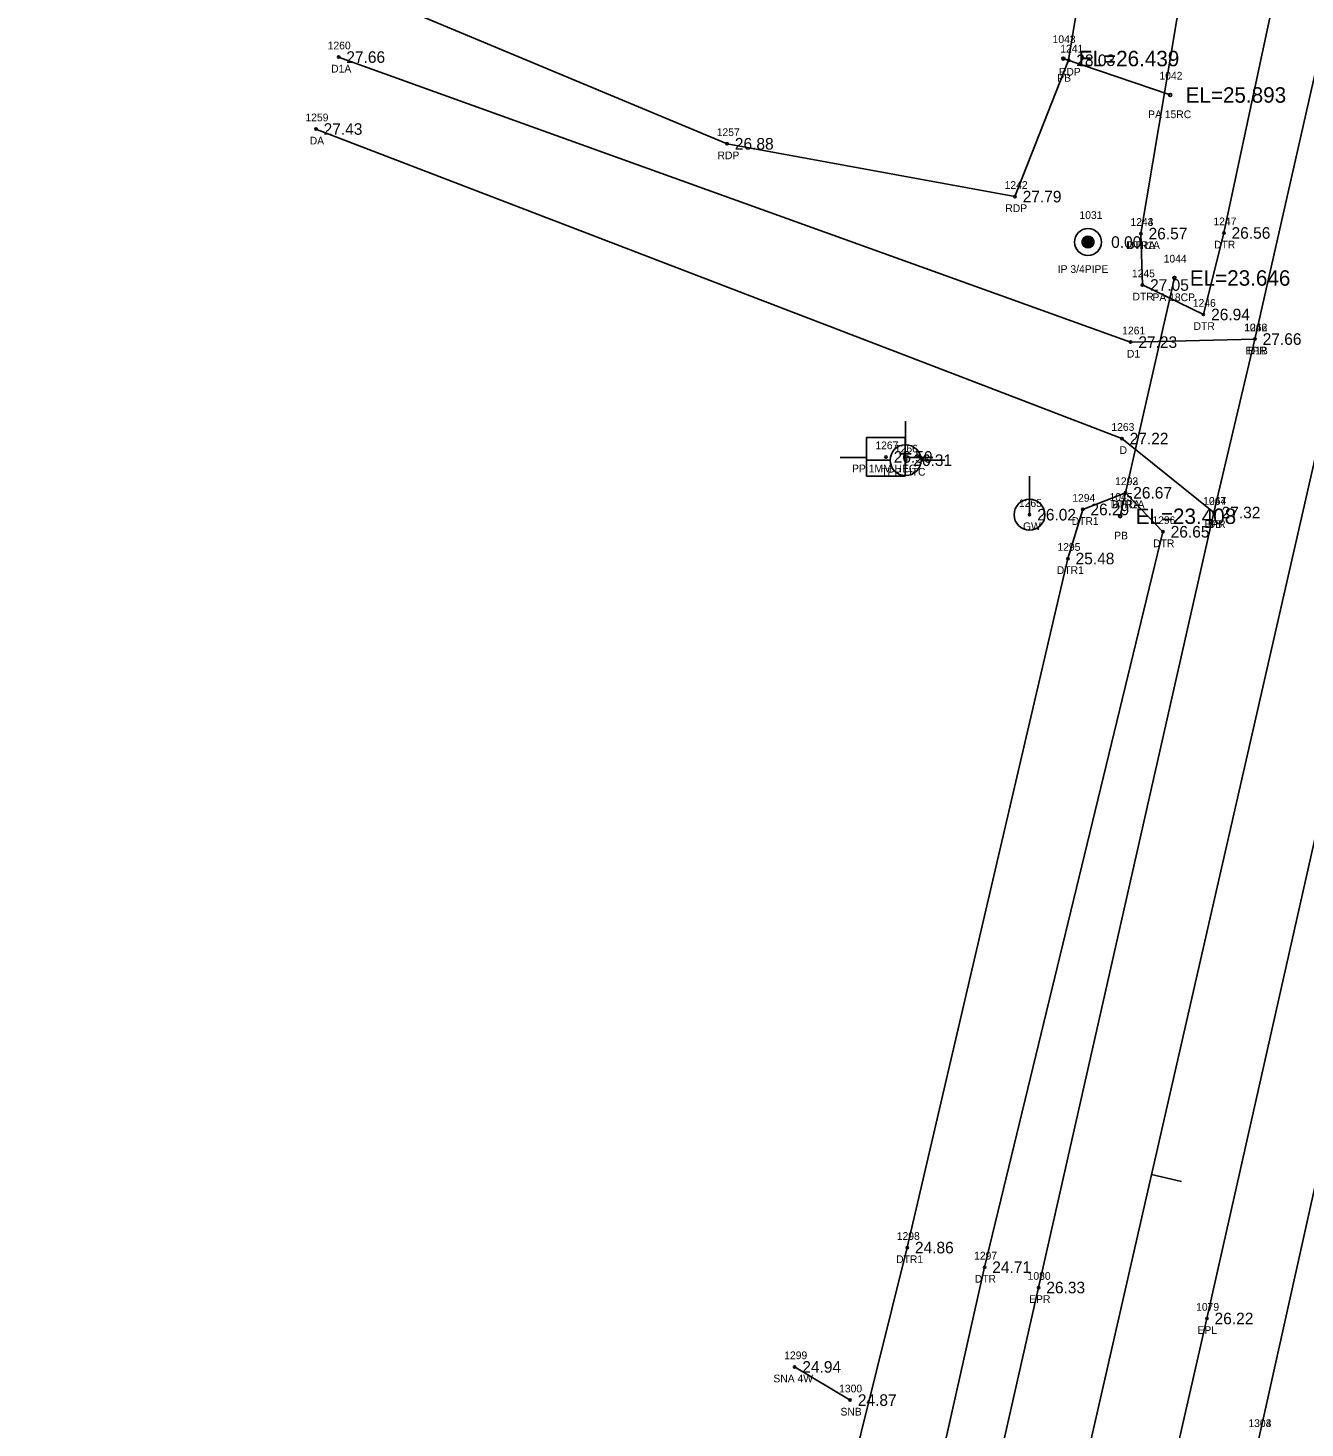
# Model space of a CAD drawing. Extents: x 2654414 to 2656963, y 761776 to 764965.
# Drawn here: x 2655843.9 to 2656009.2, y 764411.4 to 764592.8 of the extents above; entities that cross this region are included whole.
import ezdxf

# ---------------------------------------------------------------- set-up
doc = ezdxf.new("R2010")
doc.units = 0
for name, color, linetype in [('Default', 7, 'Continuous'), ('RD_EX_BldgApp', 7, 'Continuous'), ('RD_EX_BldgApp_txCode', 7, 'Continuous'), ('RD_EX_DR_ErosCtrl', 7, 'Continuous'), ('RD_EX_DR_ErosCtrl_txCode', 7, 'Continuous'), ('RD_EX_DR_Pipe', 7, 'Continuous'), ('RD_EX_DR_Pipe_txCode', 7, 'Continuous'), ('RD_EX_Driveway', 7, 'Continuous'), ('RD_EX_Driveway_txCode', 7, 'Continuous'), ('RD_EX_DV_Prop_txCode', 7, 'Continuous'), ('RD_EX_DV_PropPin', 7, 'Continuous'), ('RD_EX_H2O', 7, 'Continuous'), ('RD_EX_H2O_txCode', 7, 'Continuous'), ('RD_EX_Road', 7, 'Continuous'), ('RD_EX_Road_txCode', 7, 'Continuous'), ('RD_EX_TX_BldgApp_ELEV', 7, 'Continuous'), ('RD_EX_TX_DR_ErosCtrl_ELEV', 7, 'Continuous'), ('RD_EX_TX_Driveway_ELEV', 7, 'Continuous'), ('RD_EX_TX_DV_Prop_ELEV', 7, 'Continuous'), ('RD_EX_TX_H2O_ELEV', 7, 'Continuous'), ('RD_EX_TX_Road_ELEV', 7, 'Continuous'), ('RD_EX_TX_UT_ELEV', 7, 'Continuous'), ('RD_EX_UT', 7, 'Continuous'), ('RD_EX_UT_txCode', 7, 'Continuous'), ('RD_HC_Cl', 7, 'Continuous'), ('RD_HC_Data_Tic', 7, 'Continuous'), ('RD_HC_Survey_ELEV', 7, 'Continuous'), ('RD_SMD_Locator', 7, 'Continuous'), ('RD_TX_Pipe_ElevEX', 7, 'Continuous')]:
    doc.layers.add(name, color=color, linetype=linetype)

msp = doc.modelspace()

# ---------------------------------------------------------------- linework, layer by layer
at = {"layer": 'Default'}
msp.add_line((2656050.51, 764712.37), (2655383.26, 761787.51), dxfattribs=at)
at = {"layer": 'RD_EX_BldgApp'}
msp.add_line((2655943.15, 764419.36), (2655950.34, 764415.06), dxfattribs=at)
at = {"layer": 'RD_EX_DR_ErosCtrl'}
msp.add_lwpolyline([(2655930.28, 764725.72), (2655961.08, 764712.81), (2655949.1, 764679.46), (2655943.17, 764649.44), (2655951.78, 764644.09), (2655985.92, 764633.07), (2655978.62, 764588.6), (2655971.68, 764570.94), (2655934.42, 764577.78), (2655887.79, 764597.3)], dxfattribs=at)
at = {"layer": 'RD_EX_DR_Pipe'}
for p, q in [((2655991.77, 764584.1), (2655977.94, 764588.82)), ((2655992.32, 764560.4), (2655985.3, 764529.54)), ((2656020.76, 764488.83), (2656001.47, 764402.19))]:
    msp.add_line(p, q, dxfattribs=at)
at = {"layer": 'RD_EX_Driveway'}
for points in [[(2655884.12, 764589.01), (2655986.65, 764552.09), (2656002.75, 764552.49)], [(2655881.18, 764579.69), (2655985.53, 764539.6), (2655997.43, 764530.02)]]:
    msp.add_lwpolyline(points, dxfattribs=at)
at = {"layer": 'RD_EX_DV_PropPin'}
for p, q in [((2655980.4, 764564.85), (2655980.4, 764565.24)), ((2655980.43, 764564.75), (2655980.43, 764565.35)), ((2655980.47, 764564.68), (2655980.47, 764565.42)), ((2655980.5, 764564.62), (2655980.5, 764565.48)), ((2655980.54, 764564.57), (2655980.54, 764565.52)), ((2655980.57, 764564.53), (2655980.57, 764565.56)), ((2655980.61, 764564.5), (2655980.61, 764565.6)), ((2655980.64, 764564.47), (2655980.64, 764565.63)), ((2655980.68, 764564.44), (2655980.68, 764565.66)), ((2655980.71, 764564.41), (2655980.71, 764565.68)), ((2655980.75, 764564.39), (2655980.75, 764565.71)), ((2655980.78, 764564.37), (2655980.78, 764565.72)), ((2655980.82, 764564.36), (2655980.82, 764565.74)), ((2655980.85, 764564.34), (2655980.85, 764565.76)), ((2655980.89, 764564.33), (2655980.89, 764565.77)), ((2655980.92, 764564.32), (2655980.92, 764565.78)), ((2655980.96, 764564.31), (2655980.96, 764565.79)), ((2655980.99, 764564.3), (2655980.99, 764565.8)), ((2655981.03, 764564.3), (2655981.03, 764565.8)), ((2655981.06, 764564.29), (2655981.06, 764565.81)), ((2655981.1, 764564.29), (2655981.1, 764565.81)), ((2655981.13, 764564.29), (2655981.13, 764565.81)), ((2655981.17, 764564.29), (2655981.17, 764565.81)), ((2655981.2, 764564.29), (2655981.2, 764565.81)), ((2655981.24, 764564.3), (2655981.24, 764565.8)), ((2655981.27, 764564.3), (2655981.27, 764565.8)), ((2655981.31, 764564.31), (2655981.31, 764565.79)), ((2655981.34, 764564.32), (2655981.34, 764565.78)), ((2655981.38, 764564.33), (2655981.38, 764565.77)), ((2655981.41, 764564.34), (2655981.41, 764565.76)), ((2655981.45, 764564.36), (2655981.45, 764565.74)), ((2655981.48, 764564.37), (2655981.48, 764565.72)), ((2655981.52, 764564.39), (2655981.52, 764565.71)), ((2655981.55, 764564.41), (2655981.55, 764565.68)), ((2655981.59, 764564.44), (2655981.59, 764565.66)), ((2655981.62, 764564.47), (2655981.62, 764565.63)), ((2655981.66, 764564.5), (2655981.66, 764565.6)), ((2655981.69, 764564.53), (2655981.69, 764565.56)), ((2655981.73, 764564.57), (2655981.73, 764565.52)), ((2655981.76, 764564.62), (2655981.76, 764565.48)), ((2655981.8, 764564.68), (2655981.8, 764565.42)), ((2655981.83, 764564.75), (2655981.83, 764565.35)), ((2655981.87, 764564.85), (2655981.87, 764565.24))]:
    msp.add_line(p, q, dxfattribs=at)
for radius in [1.75, 0.761]:
    msp.add_circle((2655981.13, 764565.05), radius, dxfattribs=at)
at = {"layer": 'RD_EX_H2O'}
for points in [[(2655987.98, 764566.15), (2655998.01, 764626), (2656017.58, 764706.77), (2656029.4, 764703.4)], [(2655987.98, 764566.15), (2655988.17, 764559.49), (2655996.07, 764555.67), (2655998.72, 764566.23), (2656011.11, 764624.25), (2656029.4, 764703.4)], [(2655985.99, 764532.58), (2655990.84, 764527.53), (2655967.74, 764432.27), (2655946, 764335.4), (2655922.66, 764238.07), (2655902.06, 764145.42), (2655879.59, 764053.25), (2655859.1, 763959.14), (2655841.15, 763874.16), (2655837.57, 763865.39), (2655829.11, 763865.29), (2655761.29, 763886.78)], [(2655985.99, 764532.58), (2655980.45, 764530.42), (2655978.53, 764524.06), (2655957.73, 764434.81), (2655933.82, 764338.64), (2655911.79, 764241.24), (2655890.59, 764146.77), (2655869.91, 764054.39), (2655847.97, 763961.11)]]:
    msp.add_lwpolyline(points, dxfattribs=at)
at = {"layer": 'RD_EX_Road'}
for points in [[(2656041.72, 764723.31), (2656018.5, 764622.03), (2656002.75, 764552.49), (2655997.43, 764530.02), (2655974.74, 764429.64), (2655952.97, 764333.57), (2655930.52, 764235.7), (2655909.18, 764142.93), (2655887.93, 764050.57), (2655866.91, 763957.26), (2655846.82, 763869.53), (2655845.21, 763862.22), (2655839.99, 763839.71), (2655823.38, 763766.66), (2655801.33, 763669.93), (2655780.03, 763576.53), (2655774.26, 763551.85), (2655771.37, 763539.86), (2655759.09, 763486.9), (2655736.94, 763391.72), (2655715.19, 763296.77), (2655711.35, 763278.45)], [(2656062.87, 764717.57), (2656039.84, 764617.04), (2656035.41, 764597.94), (2656033.38, 764589.18), (2656018.27, 764522.6), (2656017.22, 764517.64), (2656011.07, 764490.22), (2655996.52, 764425.63), (2655974.03, 764327.02), (2655960.71, 764269.34), (2655951.96, 764231.59), (2655930.84, 764138.62), (2655926.81, 764121.01), (2655909.26, 764045.26), (2655908.15, 764039.87), (2655902.08, 764013.51), (2655888.19, 763952.26), (2655880.73, 763919.6), (2655875, 763893.73), (2655866.73, 763857), (2655852.89, 763796.34), (2655850.73, 763786.52)]]:
    msp.add_lwpolyline(points, dxfattribs=at)
at = {"layer": 'RD_EX_UT'}
for p, q in [((2655957.52, 764541.87), (2655957.52, 764538.8)), ((2655957.47, 764539.73), (2655952.47, 764539.73)), ((2655952.47, 764539.73), (2655952.47, 764534.73)), ((2655957.47, 764534.73), (2655957.47, 764539.73)), ((2655949.04, 764537.16), (2655952.51, 764537.16)), ((2655952.59, 764536.81), (2655955.52, 764536.81)), ((2655957.4, 764537.16), (2655961.04, 764537.16)), ((2655959.52, 764536.81), (2655962.59, 764536.81)), ((2655952.47, 764534.73), (2655957.47, 764534.73)), ((2655973.56, 764529.74), (2655973.56, 764534.74))]:
    msp.add_line(p, q, dxfattribs=at)
for centre in [(2655957.52, 764536.8), (2655973.56, 764529.74)]:
    msp.add_circle(centre, 2, dxfattribs=at)
at = {"layer": 'RD_HC_Cl'}
msp.add_line((2656050.51, 764712.37), (2655383.26, 761787.51), dxfattribs=at)
at = {"layer": 'RD_HC_Data_Tic'}
msp.add_line((2655989.35, 764444.26), (2655993.25, 764443.37), dxfattribs=at)
at = {"layer": 'RD_SMD_Locator'}
for centre, radius in [((2655884.12, 764589.01), 0.15), ((2655977.94, 764588.82), 0.2), ((2655978.62, 764588.6), 0.15), ((2655991.77, 764584.1), 0.2), ((2655881.18, 764579.69), 0.15), ((2655934.42, 764577.78), 0.15), ((2655971.68, 764570.94), 0.15), ((2655981.13, 764565.05), 0.15), ((2655987.98, 764566.15), 0.15), ((2655987.98, 764566.15), 0.15), ((2655998.72, 764566.23), 0.15), ((2655988.17, 764559.49), 0.15), ((2655992.32, 764560.4), 0.2), ((2655996.07, 764555.67), 0.15), ((2655986.65, 764552.09), 0.15), ((2656002.75, 764552.49), 0.15), ((2656002.75, 764552.49), 0.15), ((2655985.53, 764539.6), 0.15), ((2655954.98, 764537.22), 0.15), ((2655957.52, 764536.8), 0.15), ((2655985.99, 764532.58), 0.15), ((2655985.99, 764532.58), 0.15), ((2655980.45, 764530.42), 0.15), ((2655973.56, 764529.74), 0.15), ((2655985.3, 764529.54), 0.2), ((2655997.43, 764530.02), 0.15), ((2655997.43, 764530.02), 0.15), ((2655990.84, 764527.53), 0.15), ((2655978.53, 764524.06), 0.15), ((2655957.73, 764434.81), 0.15), ((2655967.74, 764432.27), 0.15), ((2655974.74, 764429.64), 0.15), ((2655996.52, 764425.63), 0.15), ((2655943.15, 764419.36), 0.15), ((2655950.34, 764415.06), 0.15)]:
    msp.add_circle(centre, radius, dxfattribs=at)

# ---------------------------------------------------------------- texts
at = {"layer": 'RD_EX_BldgApp_txCode'}
for s, p in [('1299', (2655941.81, 764420.36)), ('SNA 4W', (2655940.41, 764417.36)), ('1300', (2655948.92, 764416.06)), ('SNB', (2655949.09, 764413.06))]:
    msp.add_text(s, height=1, dxfattribs=at).set_placement(p)
at = {"layer": 'RD_EX_DR_ErosCtrl_txCode'}
for s, p in [('1241', (2655977.55, 764589.6)), ('RDP', (2655977.37, 764586.6)), ('1257', (2655933.07, 764578.78)), ('RDP', (2655933.17, 764575.78)), ('1242', (2655970.34, 764571.94)), ('RDP', (2655970.43, 764568.94))]:
    msp.add_text(s, height=1, dxfattribs=at).set_placement(p)
at = {"layer": 'RD_EX_DR_Pipe_txCode'}
for s, p in [('1043', (2655976.55, 764590.82)), ('PB', (2655977.16, 764585.82)), ('1042', (2655990.38, 764586.1)), ('PA 15RC', (2655988.92, 764581.1)), ('1044', (2655990.93, 764562.4)), ('PA 18CP', (2655989.48, 764557.4)), ('1045', (2655983.92, 764531.54)), ('PB', (2655984.53, 764526.54))]:
    msp.add_text(s, height=1, dxfattribs=at).set_placement(p)
at = {"layer": 'RD_EX_Driveway_txCode'}
for s, p in [('1260', (2655882.71, 764590.01)), ('D1A', (2655883.16, 764587.01)), ('1259', (2655879.83, 764580.69)), ('DA', (2655880.38, 764577.69)), ('1261', (2655985.56, 764553.09)), ('1262', (2656001.38, 764553.49)), ('D1', (2655986.17, 764550.09)), ('D1B', (2656001.81, 764550.49)), ('1263', (2655984.16, 764540.6)), ('D', (2655985.22, 764537.6)), ('1264', (2655996.06, 764531.02)), ('DB', (2655996.65, 764528.02))]:
    msp.add_text(s, height=1, dxfattribs=at).set_placement(p)
at = {"layer": 'RD_EX_DV_Prop_txCode'}
for s, p in [('1031', (2655980.03, 764568.05)), ('IP 3/4PIPE', (2655977.22, 764561.05))]:
    msp.add_text(s, height=1, dxfattribs=at).set_placement(p)
at = {"layer": 'RD_EX_H2O_txCode'}
for s, p in [('1243', (2655986.63, 764567.15)), ('1244', (2655986.63, 764567.15)), ('1247', (2655997.37, 764567.23)), ('DTR1A', (2655986.06, 764564.15)), ('DTRA', (2655986.22, 764564.15)), ('DTR', (2655997.45, 764564.23)), ('1245', (2655986.82, 764560.49)), ('DTR', (2655986.9, 764557.49)), ('1246', (2655994.7, 764556.67)), ('DTR', (2655994.8, 764553.67)), ('1292', (2655984.65, 764533.58)), ('1293', (2655984.65, 764533.58)), ('1294', (2655979.1, 764531.42)), ('DTR1A', (2655984.07, 764530.58)), ('DTRA', (2655984.24, 764530.58)), ('DTR1', (2655979.02, 764528.42)), ('1296', (2655989.47, 764528.53)), ('1295', (2655977.18, 764525.06)), ('DTR', (2655989.57, 764525.53)), ('DTR1', (2655977.1, 764522.06)), ('1298', (2655956.38, 764435.81)), ('1297', (2655966.39, 764433.27)), ('DTR1', (2655956.29, 764432.81)), ('DTR', (2655966.47, 764430.27)), ('1303', (2656001.9, 764411.57)), ('1304', (2656001.9, 764411.57))]:
    msp.add_text(s, height=1, dxfattribs=at).set_placement(p)
at = {"layer": 'RD_EX_Road_txCode'}
for s, p in [('1046', (2656001.34, 764553.49)), ('EPR', (2656001.52, 764550.49)), ('1047', (2655996.05, 764531.02)), ('EPR', (2655996.2, 764528.02)), ('1080', (2655973.32, 764430.64)), ('EPR', (2655973.52, 764427.64)), ('1079', (2655995.13, 764426.63)), ('EPL', (2655995.31, 764423.63))]:
    msp.add_text(s, height=1, dxfattribs=at).set_placement(p)
at = {"layer": 'RD_EX_TX_BldgApp_ELEV'}
for s, p in [('24.94', (2655944.15, 764418.61)), ('24.87', (2655951.34, 764414.31))]:
    msp.add_text(s, height=1.5, dxfattribs=at).set_placement(p)
at = {"layer": 'RD_EX_TX_DR_ErosCtrl_ELEV'}
for s, p in [('28.03', (2655979.62, 764587.85)), ('26.88', (2655935.42, 764577.03)), ('27.79', (2655972.68, 764570.19))]:
    msp.add_text(s, height=1.5, dxfattribs=at).set_placement(p)
at = {"layer": 'RD_EX_TX_Driveway_ELEV'}
for s, p in [('27.66', (2655885.12, 764588.26)), ('27.43', (2655882.18, 764578.94)), ('27.23', (2655987.65, 764551.34)), ('27.66', (2656003.75, 764551.74)), ('27.22', (2655986.53, 764538.85)), ('27.32', (2655998.43, 764529.27))]:
    msp.add_text(s, height=1.5, dxfattribs=at).set_placement(p)
at = {"layer": 'RD_EX_TX_DV_Prop_ELEV'}
msp.add_text('0.00', height=1.5, dxfattribs=at).set_placement((2655984.13, 764564.3))
at = {"layer": 'RD_EX_TX_H2O_ELEV'}
for s, p in [('26.57', (2655988.98, 764565.4)), ('26.57', (2655988.98, 764565.4)), ('26.56', (2655999.72, 764565.48)), ('27.05', (2655989.17, 764558.74)), ('26.94', (2655997.07, 764554.92)), ('26.67', (2655986.99, 764531.83)), ('26.67', (2655986.99, 764531.83)), ('26.29', (2655981.45, 764529.67)), ('26.65', (2655991.84, 764526.78)), ('25.48', (2655979.53, 764523.31)), ('24.86', (2655958.73, 764434.06)), ('24.71', (2655968.74, 764431.52))]:
    msp.add_text(s, height=1.5, dxfattribs=at).set_placement(p)
at = {"layer": 'RD_EX_TX_Road_ELEV'}
for s, p in [('27.66', (2656003.75, 764551.74)), ('27.32', (2655998.43, 764529.27)), ('26.33', (2655975.74, 764428.89)), ('26.22', (2655997.52, 764424.88))]:
    msp.add_text(s, height=1.5, dxfattribs=at).set_placement(p)
at = {"layer": 'RD_EX_TX_UT_ELEV'}
for s, p in [('26.31', (2655958.52, 764536.05)), ('26.02', (2655974.56, 764528.99))]:
    msp.add_text(s, height=1.5, dxfattribs=at).set_placement(p)
at = {"layer": 'RD_EX_UT'}
msp.add_text('T', height=2, dxfattribs=at).set_placement((2655956.67, 764535.75))
at = {"layer": 'RD_EX_UT_txCode'}
for s, p in [('1267', (2655953.61, 764538.22)), ('1266', (2655956.13, 764537.8)), ('PP 1MM HEC', (2655950.59, 764535.22)), ('TPP HTC', (2655954.37, 764534.8)), ('1265', (2655972.19, 764530.74)), ('GW', (2655972.72, 764527.74))]:
    msp.add_text(s, height=1, dxfattribs=at).set_placement(p)
at = {"layer": 'RD_HC_Survey_ELEV'}
msp.add_text('26.50', height=1.5, dxfattribs=at).set_placement((2655955.98, 764536.47))
at = {"layer": 'RD_TX_Pipe_ElevEX'}
for s, p in [('EL=26.439', (2655979.94, 764587.82)), ('EL=25.893', (2655993.77, 764583.1)), ('EL=23.646', (2655994.32, 764559.4)), ('EL=23.408', (2655987.3, 764528.54))]:
    msp.add_text(s, height=2, dxfattribs=at).set_placement(p)

doc.saveas('drawing.dxf')
